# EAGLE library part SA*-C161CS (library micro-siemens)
16bit Low-Cost Microcontroller mit CAN
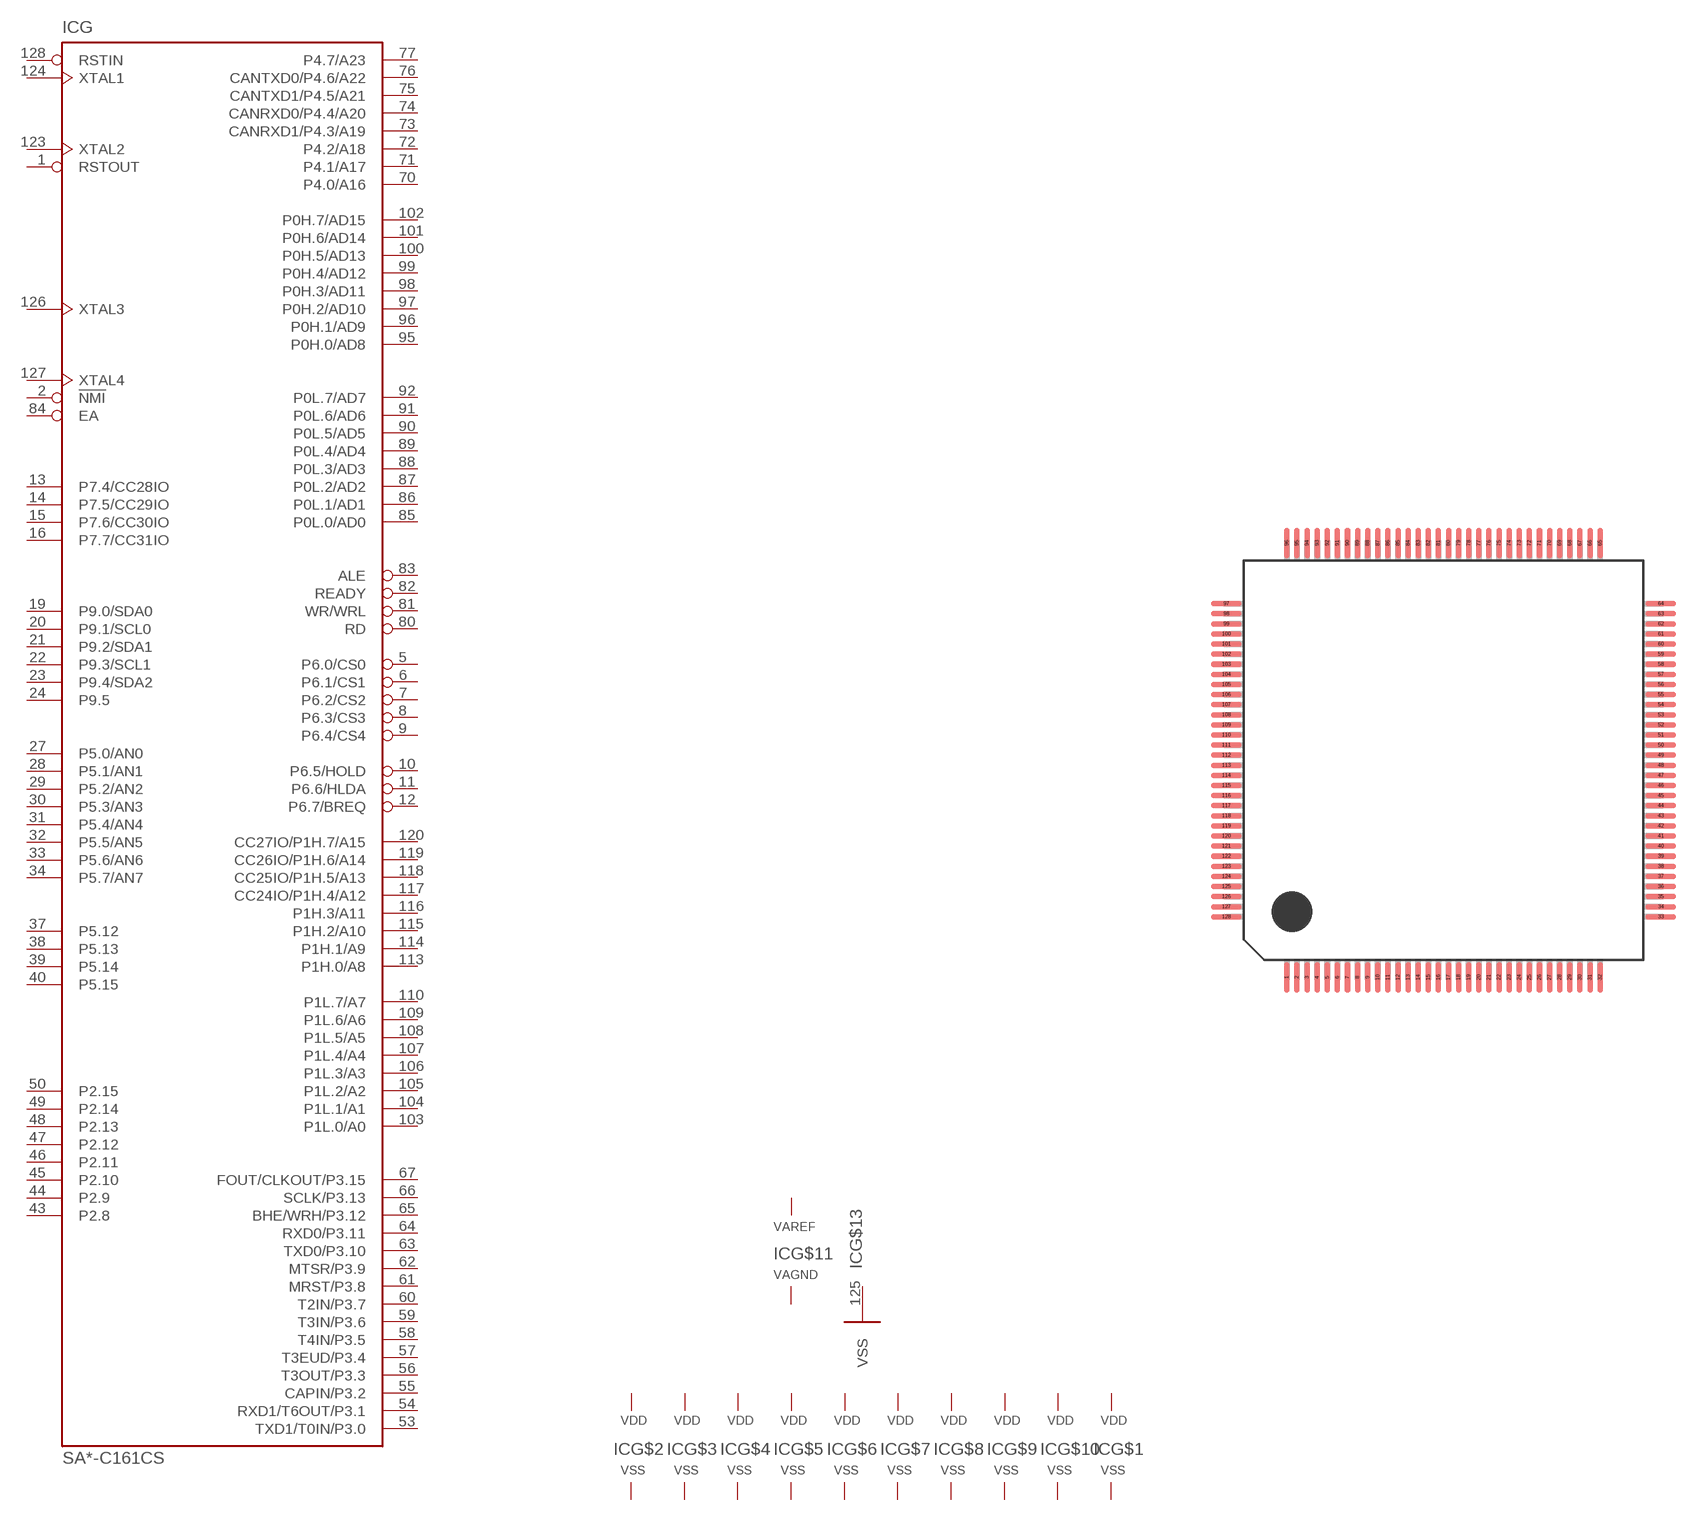
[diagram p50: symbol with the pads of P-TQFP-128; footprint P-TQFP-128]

Designator prefix IC; gates G=SABC161CS G$1=PWR G$2=PWR G$3=PWR G$4=PWR G$5=PWR G$6=PWR G$7=PWR G$8=PWR G$9=PWR G$10=PWR G$11=APWR G$13=VSS-1

## SAB-C161CSSMD (OC_FARNELL: unknown; OC_NEWARK: unknown), SAF-C161CSSMD (OC_FARNELL: unknown; OC_NEWARK: unknown), SAK-C161CSSMD (OC_FARNELL: 1472739; OC_NEWARK: unknown)  [P-TQFP-128]
1  G:RSTOUT  out
2  G:!NMI  in
3  G$2:VSS  pwr
4  G$2:VDD  pwr
5  G:P6.0/CS0  out
6  G:P6.1/CS1  out
7  G:P6.2/CS2  out
8  G:P6.3/CS3  out
9  G:P6.4/CS4  out
10  G:P6.5/HOLD  out
11  G:P6.6/HLDA  out
12  G:P6.7/BREQ  out
13  G:P7.4/CC28IO
14  G:P7.5/CC29IO
15  G:P7.6/CC30IO
16  G:P7.7/CC31IO
17  G$3:VSS  pwr
18  G$3:VDD  pwr
19  G:P9.0/SDA0
20  G:P9.1/SCL0
21  G:P9.2/SDA1
22  G:P9.3/SCL1
23  G:P9.4/SDA2
24  G:P9.5
25  G$4:VSS  pwr
26  G$4:VDD  pwr
27  G:P5.0/AN0  in
28  G:P5.1/AN1  in
29  G:P5.2/AN2  in
30  G:P5.3/AN3  in
31  G:P5.4/AN4  in
32  G:P5.5/AN5  in
33  G:P5.6/AN6  in
34  G:P5.7/AN7  in
35  G$11:VAREF  pwr
36  G$11:VAGND  pwr
37  G:P5.12  in
38  G:P5.13  in
39  G:P5.14  in
40  G:P5.15  in
41  G$5:VSS  pwr
42  G$5:VDD  pwr
43  G:P2.8  in
44  G:P2.9  in
45  G:P2.10  in
46  G:P2.11  in
47  G:P2.12  in
48  G:P2.13  in
49  G:P2.14  in
50  G:P2.15  in
51  G$6:VSS  pwr
52  G$6:VDD  pwr
53  G:TXD1/T0IN/P3.0  in
54  G:RXD1/T6OUT/P3.1  in
55  G:CAPIN/P3.2  in
56  G:T3OUT/P3.3  in
57  G:T3EUD/P3.4  in
58  G:T4IN/P3.5  in
59  G:T3IN/P3.6  in
60  G:T2IN/P3.7  in
61  G:MRST/P3.8  in
62  G:MTSR/P3.9  in
63  G:TXD0/P3.10  in
64  G:RXD0/P3.11  in
65  G:BHE/WRH/P3.12  in
66  G:SCLK/P3.13  in
67  G:FOUT/CLKOUT/P3.15  in
68  G$10:VDD  pwr
69  G$10:VSS  pwr
70  G:P4.0/A16
71  G:P4.1/A17
72  G:P4.2/A18
73  G:CANRXD1/P4.3/A19
74  G:CANRXD0/P4.4/A20
75  G:CANTXD1/P4.5/A21
76  G:CANTXD0/P4.6/A22
77  G:P4.7/A23
78  G$9:VDD  pwr
79  G$9:VSS  pwr
80  G:RD  out
81  G:WR/WRL  out
82  G:READY  out
83  G:ALE  out
84  G:EA  in
85  G:P0L.0/AD0
86  G:P0L.1/AD1
87  G:P0L.2/AD2
88  G:P0L.3/AD3
89  G:P0L.4/AD4
90  G:P0L.5/AD5
91  G:P0L.6/AD6
92  G:P0L.7/AD7
93  G$7:VDD  pwr
94  G$7:VSS  pwr
95  G:P0H.0/AD8
96  G:P0H.1/AD9
97  G:P0H.2/AD10
98  G:P0H.3/AD11
99  G:P0H.4/AD12
100  G:P0H.5/AD13
101  G:P0H.6/AD14
102  G:P0H.7/AD15
103  G:P1L.0/A0
104  G:P1L.1/A1
105  G:P1L.2/A2
106  G:P1L.3/A3
107  G:P1L.4/A4
108  G:P1L.5/A5
109  G:P1L.6/A6
110  G:P1L.7/A7
111  G$8:VDD  pwr
112  G$8:VSS  pwr
113  G:P1H.0/A8
114  G:P1H.1/A9
115  G:P1H.2/A10
116  G:P1H.3/A11
117  G:CC24IO/P1H.4/A12
118  G:CC25IO/P1H.5/A13
119  G:CC26IO/P1H.6/A14
120  G:CC27IO/P1H.7/A15
121  G$1:VDD  pwr
122  G$1:VSS  pwr
123  G:XTAL2
124  G:XTAL1
125  G$13:VSS  pwr
126  G:XTAL3
127  G:XTAL4
128  G:RSTIN

## Footprint P-TQFP-128 (pad centres in mm)
P-TQFP-128 with rounded pads
smd 0.27 x 1.5: 1 -6.48,-10.75; 2 -5.98,-10.75; 3 -5.48,-10.75; 4 -4.98,-10.75; 5 -4.48,-10.75; 6 -3.98,-10.75; 7 -3.48,-10.75; 8 -2.98,-10.75; 9 -2.48,-10.75; 10 -1.98,-10.75; 11 -1.48,-10.75; 12 -0.98,-10.75; 13 -0.48,-10.75; 14 0.02,-10.75; 15 0.52,-10.75; 16 1.02,-10.75; 17 1.52,-10.75; 18 2.02,-10.75; 19 2.52,-10.75; 20 3.02,-10.75; 21 3.52,-10.75; 22 4.02,-10.75; 23 4.52,-10.75; 24 5.02,-10.75; 25 5.52,-10.75; 26 6.02,-10.75; 27 6.52,-10.75; 28 7.02,-10.75; 29 7.52,-10.75; 30 8.02,-10.75; 31 8.52,-10.75; 32 9.02,-10.75; 65 9.02,10.75; 66 8.52,10.75; 67 8.02,10.75; 68 7.52,10.75; 69 7.02,10.75; 70 6.52,10.75; 71 6.02,10.75; 72 5.52,10.75; 73 5.02,10.75; 74 4.52,10.75; 75 4.02,10.75; 76 3.52,10.75; 77 3.02,10.75; 78 2.52,10.75; 79 2.02,10.75; 80 1.52,10.75; 81 1.02,10.75; 82 0.52,10.75; 83 0.02,10.75; 84 -0.48,10.75; 85 -0.98,10.75; 86 -1.48,10.75; 87 -1.98,10.75; 88 -2.48,10.75; 89 -2.98,10.75; 90 -3.48,10.75; 91 -3.98,10.75; 92 -4.48,10.75; 93 -4.98,10.75; 94 -5.48,10.75; 95 -5.98,10.75; 96 -6.48,10.75
smd 1.5 x 0.27: 33 12.02,-7.75; 34 12.02,-7.25; 35 12.02,-6.75; 36 12.02,-6.25; 37 12.02,-5.75; 38 12.02,-5.25; 39 12.02,-4.75; 40 12.02,-4.25; 41 12.02,-3.75; 42 12.02,-3.25; 43 12.02,-2.75; 44 12.02,-2.25; 45 12.02,-1.75; 46 12.02,-1.25; 47 12.02,-0.75; 48 12.02,-0.25; 49 12.02,0.25; 50 12.02,0.75; 51 12.02,1.25; 52 12.02,1.75; 53 12.02,2.25; 54 12.02,2.75; 55 12.02,3.25; 56 12.02,3.75; 57 12.02,4.25; 58 12.02,4.75; 59 12.02,5.25; 60 12.02,5.75; 61 12.02,6.25; 62 12.02,6.75; 63 12.02,7.25; 64 12.02,7.75; 97 -9.48,7.75; 98 -9.48,7.25; 99 -9.48,6.75; 100 -9.48,6.25; 101 -9.48,5.75; 102 -9.48,5.25; 103 -9.48,4.75; 104 -9.48,4.25; 105 -9.48,3.75; 106 -9.48,3.25; 107 -9.48,2.75; 108 -9.48,2.25; 109 -9.48,1.75; 110 -9.48,1.25; 111 -9.48,0.75; 112 -9.48,0.25; 113 -9.48,-0.25; 114 -9.48,-0.75; 115 -9.48,-1.25; 116 -9.48,-1.75; 117 -9.48,-2.25; 118 -9.48,-2.75; 119 -9.48,-3.25; 120 -9.48,-3.75; 121 -9.48,-4.25; 122 -9.48,-4.75; 123 -9.48,-5.25; 124 -9.48,-5.75; 125 -9.48,-6.25; 126 -9.48,-6.75; 127 -9.48,-7.25; 128 -9.48,-7.75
